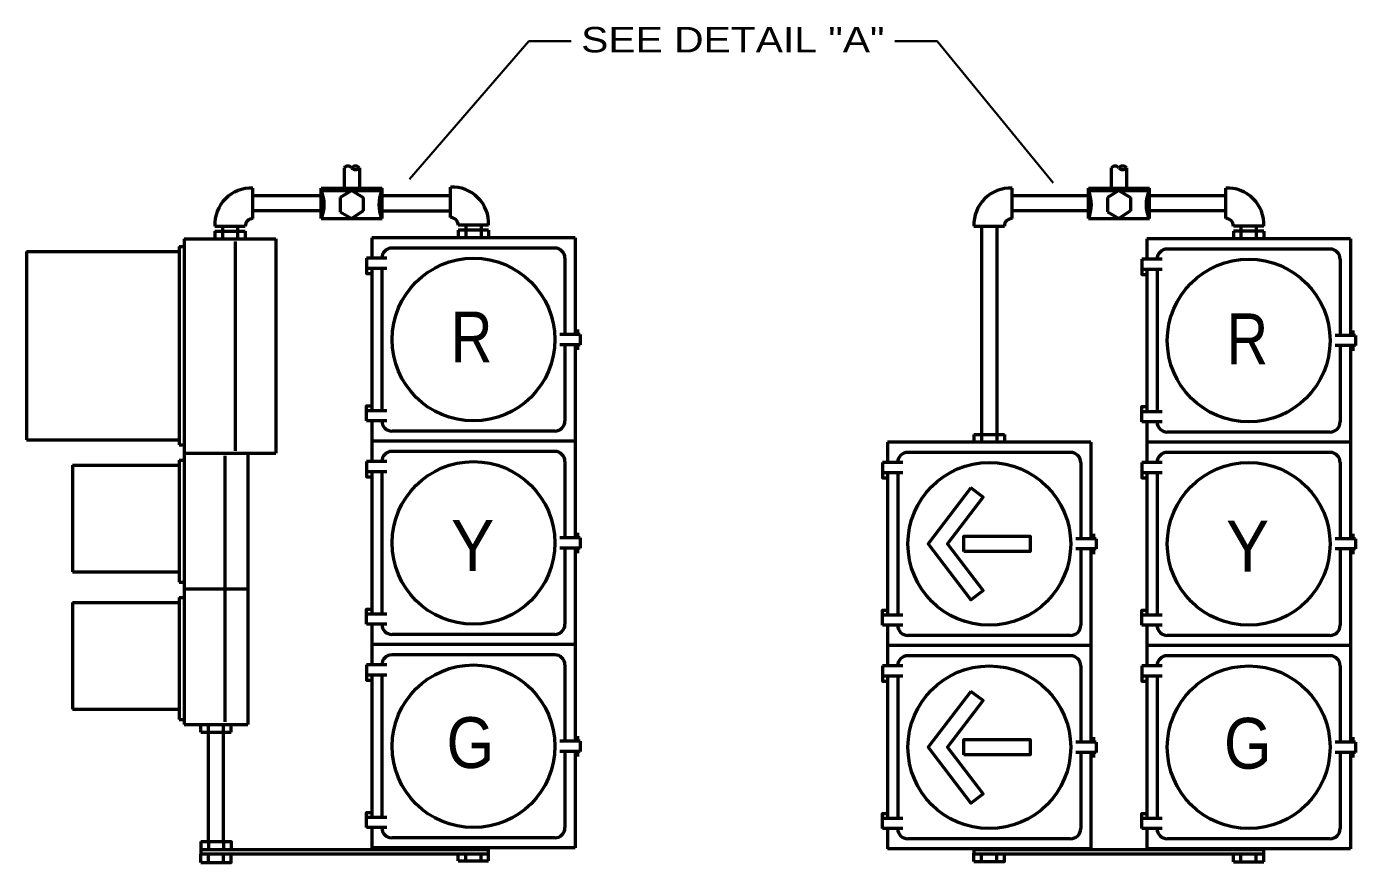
# Model space of a CAD drawing. Extents: x -382 to 473, y -132 to 412.
# Drawn here: x -262.8 to -106, y 137.8 to 236.4 of the extents above; entities that cross this region are included whole.
import ezdxf
from ezdxf.enums import TextEntityAlignment as Align

# ---------------------------------------------------------------- set-up
doc = ezdxf.new("R2010")
doc.units = 0
doc.header["$LTSCALE"] = 1.1
doc.layers.add('1', color=7, linetype='Continuous', lineweight=53)

msp = doc.modelspace()

# ---------------------------------------------------------------- linework, layer by layer
at = {"layer": '1', "lineweight": 35}
for p, q in [((-203.526, 234.737), (-217.631, 218.457)), ((-203.526, 234.737), (-198.535, 234.737)), ((-160.344, 234.737), (-155.353, 234.737)), ((-155.353, 234.737), (-141.683, 218.023))]:
    msp.add_line(p, q, dxfattribs=at)
at = {"layer": '1'}
for p, q in [((-225.335, 219.784), (-225.335, 217.384)), ((-223.535, 219.784), (-223.535, 217.384)), ((-134.828, 219.784), (-134.828, 217.384)), ((-133.028, 219.784), (-133.028, 217.384)), ((-236.09, 213.784), (-236.09, 217.384)), ((-236.09, 216.494), (-228.035, 216.494)), ((-228.035, 217.384), (-220.835, 217.384)), ((-228.035, 217.084), (-220.835, 217.084)), ((-224.435, 217.084), (-225.785, 216.274)), ((-224.435, 217.084), (-223.085, 216.274)), ((-220.835, 213.784), (-220.835, 217.384)), ((-220.835, 216.494), (-212.78, 216.494)), ((-212.78, 213.908), (-212.78, 217.508)), ((-146.528, 213.784), (-146.528, 217.384)), ((-137.528, 216.484), (-146.528, 216.484)), ((-137.528, 217.384), (-130.328, 217.384)), ((-137.528, 217.084), (-130.328, 217.084)), ((-133.928, 217.084), (-135.278, 216.274)), ((-133.928, 217.084), (-132.578, 216.274)), ((-130.328, 213.784), (-130.328, 217.384)), ((-121.328, 216.484), (-130.328, 216.484)), ((-121.328, 213.794), (-121.328, 217.394)), ((-225.785, 216.274), (-225.785, 214.594)), ((-223.085, 216.274), (-223.085, 214.714)), ((-135.278, 216.274), (-135.278, 214.594)), ((-132.578, 216.274), (-132.578, 214.714)), ((-228.035, 214.684), (-236.09, 214.684)), ((-228.035, 213.784), (-220.835, 213.784)), ((-225.785, 214.594), (-224.435, 213.784)), ((-223.085, 214.714), (-224.435, 213.784)), ((-220.835, 214.694), (-212.78, 214.694)), ((-137.528, 214.684), (-146.528, 214.684)), ((-137.528, 213.784), (-130.328, 213.784)), ((-135.278, 214.594), (-133.928, 213.784)), ((-132.578, 214.714), (-133.928, 213.784)), ((-121.328, 214.684), (-130.328, 214.684)), ((-240.59, 212.884), (-236.99, 212.884)), ((-240.59, 212.284), (-240.59, 211.384)), ((-240.59, 212.284), (-236.99, 212.284)), ((-239.69, 212.884), (-239.69, 211.384)), ((-237.89, 212.884), (-237.89, 211.384)), ((-236.99, 212.284), (-236.99, 211.384)), ((-208.28, 213.008), (-211.88, 213.008)), ((-211.88, 212.408), (-211.88, 211.508)), ((-208.28, 212.408), (-211.88, 212.408)), ((-210.98, 213.008), (-210.98, 211.508)), ((-209.18, 213.008), (-209.18, 211.508)), ((-208.28, 212.408), (-208.28, 211.508)), ((-151.028, 212.884), (-147.428, 212.884)), ((-150.128, 212.884), (-150.128, 187.394)), ((-148.328, 212.884), (-148.328, 187.394)), ((-116.828, 212.894), (-120.428, 212.894)), ((-120.428, 212.294), (-120.428, 211.394)), ((-116.828, 212.294), (-120.428, 212.294)), ((-119.528, 212.894), (-119.528, 211.394)), ((-117.728, 212.894), (-117.728, 211.394)), ((-116.828, 212.294), (-116.828, 211.394)), ((-244.79, 210.484), (-244.19, 210.484)), ((-244.79, 210.484), (-244.79, 187.084)), ((-244.19, 211.384), (-244.19, 154.084)), ((-244.19, 211.384), (-233.39, 211.384)), ((-238.19, 211.084), (-238.19, 186.388)), ((-233.39, 211.384), (-233.39, 186.088)), ((-198.08, 211.508), (-222.08, 211.508)), ((-222.08, 211.508), (-222.08, 209.108)), ((-200.48, 210.308), (-219.68, 210.308)), ((-198.08, 211.508), (-198.08, 200.108)), ((-106.628, 211.394), (-130.628, 211.394)), ((-130.628, 211.394), (-130.628, 208.994)), ((-109.028, 210.194), (-128.228, 210.194)), ((-106.628, 211.394), (-106.628, 199.994)), ((-262.79, 209.884), (-244.79, 209.884)), ((-262.79, 209.884), (-262.79, 187.684)), ((-220.28, 209.108), (-222.68, 209.108)), ((-199.28, 209.108), (-199.28, 200.108)), ((-128.828, 208.994), (-131.228, 208.994)), ((-107.828, 208.994), (-107.828, 199.994)), ((-220.28, 207.908), (-222.68, 207.908)), ((-222.08, 207.908), (-222.08, 191.108)), ((-220.88, 207.908), (-220.88, 191.108)), ((-128.828, 207.794), (-131.228, 207.794)), ((-130.628, 207.794), (-130.628, 190.994)), ((-129.428, 207.794), (-129.428, 190.994)), ((-197.78, 200.708), (-197.78, 200.108)), ((-197.48, 200.108), (-199.88, 200.108)), ((-197.48, 200.108), (-197.48, 198.908)), ((-106.028, 199.994), (-108.428, 199.994)), ((-106.328, 200.594), (-106.328, 199.994)), ((-106.028, 199.994), (-106.028, 198.794)), ((-197.48, 198.908), (-199.88, 198.908)), ((-199.28, 198.908), (-199.28, 189.908)), ((-198.08, 198.908), (-198.08, 187.508)), ((-197.78, 198.908), (-197.78, 198.308)), ((-106.028, 198.794), (-108.428, 198.794)), ((-107.828, 198.794), (-107.828, 189.794)), ((-106.628, 198.794), (-106.628, 187.394)), ((-106.328, 198.794), (-106.328, 198.194)), ((-220.28, 191.108), (-222.68, 191.108)), ((-220.28, 189.908), (-222.68, 189.908)), ((-222.08, 189.908), (-222.08, 187.508)), ((-128.828, 190.994), (-131.228, 190.994)), ((-128.828, 189.794), (-131.228, 189.794)), ((-130.628, 189.794), (-130.628, 187.394)), ((-200.48, 188.708), (-219.68, 188.708)), ((-151.028, 188.294), (-151.028, 187.394)), ((-151.028, 188.294), (-147.428, 188.294)), ((-147.428, 188.294), (-147.428, 187.394)), ((-109.028, 188.594), (-128.228, 188.594)), ((-262.79, 187.684), (-244.79, 187.684)), ((-244.79, 187.084), (-244.19, 187.084)), ((-198.08, 187.508), (-222.08, 187.508)), ((-222.08, 187.508), (-222.08, 185.108)), ((-198.08, 187.508), (-198.08, 176.108)), ((-137.228, 187.394), (-161.228, 187.394)), ((-161.228, 187.394), (-161.228, 184.994)), ((-137.228, 187.394), (-137.228, 175.994)), ((-106.628, 187.394), (-130.628, 187.394)), ((-130.628, 187.394), (-130.628, 184.994)), ((-106.628, 187.394), (-106.628, 175.994)), ((-244.79, 185.284), (-244.79, 170.884)), ((-244.79, 185.284), (-244.19, 185.284)), ((-244.19, 186.088), (-233.39, 186.088)), ((-239.39, 185.788), (-239.39, 154.384)), ((-236.69, 186.088), (-236.69, 154.084)), ((-220.28, 185.108), (-222.68, 185.108)), ((-200.48, 186.308), (-219.68, 186.308)), ((-199.28, 185.108), (-199.28, 176.108)), ((-159.428, 184.994), (-161.828, 184.994)), ((-139.628, 186.194), (-158.828, 186.194)), ((-138.428, 184.994), (-138.428, 175.994)), ((-128.828, 184.994), (-131.228, 184.994)), ((-109.028, 186.194), (-128.228, 186.194)), ((-107.828, 184.994), (-107.828, 175.994)), ((-257.39, 184.684), (-244.79, 184.684)), ((-257.39, 184.684), (-257.39, 172.084)), ((-220.28, 183.908), (-222.68, 183.908)), ((-222.08, 183.908), (-222.08, 167.108)), ((-220.88, 183.908), (-220.88, 167.108)), ((-159.428, 183.794), (-161.828, 183.794)), ((-161.228, 183.794), (-161.228, 166.994)), ((-160.028, 183.794), (-160.028, 166.994)), ((-128.828, 183.794), (-131.228, 183.794)), ((-130.628, 183.794), (-130.628, 166.994)), ((-129.428, 183.794), (-129.428, 166.994)), ((-197.48, 176.108), (-199.88, 176.108)), ((-197.78, 176.708), (-197.78, 176.108)), ((-197.48, 176.108), (-197.48, 174.908)), ((-136.628, 175.994), (-139.028, 175.994)), ((-136.928, 176.594), (-136.928, 175.994)), ((-136.628, 175.994), (-136.628, 174.794)), ((-106.028, 175.994), (-108.428, 175.994)), ((-106.328, 176.594), (-106.328, 175.994)), ((-106.028, 175.994), (-106.028, 174.794)), ((-197.48, 174.908), (-199.88, 174.908)), ((-199.28, 174.908), (-199.28, 165.908)), ((-198.08, 174.908), (-198.08, 163.508)), ((-197.78, 174.908), (-197.78, 174.308)), ((-136.628, 174.794), (-139.028, 174.794)), ((-138.428, 174.794), (-138.428, 165.794)), ((-137.228, 174.794), (-137.228, 163.394)), ((-136.928, 174.794), (-136.928, 174.194)), ((-106.028, 174.794), (-108.428, 174.794)), ((-107.828, 174.794), (-107.828, 165.794)), ((-106.628, 174.794), (-106.628, 163.394)), ((-106.328, 174.794), (-106.328, 174.194)), ((-257.39, 172.084), (-244.79, 172.084)), ((-244.79, 170.884), (-244.19, 170.884)), ((-244.19, 170.08), (-236.69, 170.08)), ((-257.39, 168.484), (-244.79, 168.484)), ((-257.39, 168.484), (-257.39, 155.884)), ((-244.79, 169.084), (-244.79, 154.684)), ((-244.79, 169.084), (-244.19, 169.084)), ((-220.28, 167.108), (-222.68, 167.108)), ((-159.428, 166.994), (-161.828, 166.994)), ((-128.828, 166.994), (-131.228, 166.994)), ((-220.28, 165.908), (-222.68, 165.908)), ((-222.08, 165.908), (-222.08, 163.508)), ((-200.48, 164.708), (-219.68, 164.708)), ((-159.428, 165.794), (-161.828, 165.794)), ((-161.228, 165.794), (-161.228, 163.394)), ((-128.828, 165.794), (-131.228, 165.794)), ((-130.628, 165.794), (-130.628, 163.394)), ((-198.08, 163.508), (-222.08, 163.508)), ((-222.08, 163.508), (-222.08, 161.108)), ((-198.08, 163.508), (-198.08, 152.108)), ((-137.228, 163.394), (-161.228, 163.394)), ((-161.228, 163.394), (-161.228, 160.994)), ((-139.628, 164.594), (-158.828, 164.594)), ((-137.228, 163.394), (-137.228, 151.994)), ((-106.628, 163.394), (-130.628, 163.394)), ((-130.628, 163.394), (-130.628, 160.994)), ((-109.028, 164.594), (-128.228, 164.594)), ((-106.628, 163.394), (-106.628, 151.994)), ((-200.48, 162.308), (-219.68, 162.308)), ((-139.628, 162.194), (-158.828, 162.194)), ((-109.028, 162.194), (-128.228, 162.194)), ((-220.28, 161.108), (-222.68, 161.108)), ((-220.28, 159.908), (-222.68, 159.908)), ((-222.08, 159.908), (-222.08, 143.108)), ((-220.88, 159.908), (-220.88, 143.108)), ((-199.28, 161.108), (-199.28, 152.108)), ((-159.428, 160.994), (-161.828, 160.994)), ((-138.428, 160.994), (-138.428, 151.994)), ((-128.828, 160.994), (-131.228, 160.994)), ((-107.828, 160.994), (-107.828, 151.994)), ((-159.428, 159.794), (-161.828, 159.794)), ((-161.228, 159.794), (-161.228, 142.994)), ((-160.028, 159.794), (-160.028, 142.994)), ((-128.828, 159.794), (-131.228, 159.794)), ((-130.628, 159.794), (-130.628, 142.994)), ((-129.428, 159.794), (-129.428, 142.994)), ((-257.39, 155.884), (-244.79, 155.884)), ((-244.79, 154.684), (-244.19, 154.684)), ((-244.19, 154.084), (-236.69, 154.084)), ((-242.24, 153.19), (-242.24, 154.09)), ((-238.64, 153.19), (-238.64, 154.09)), ((-242.24, 153.19), (-238.64, 153.19)), ((-197.48, 152.108), (-199.88, 152.108)), ((-197.78, 152.708), (-197.78, 152.108)), ((-197.48, 152.108), (-197.48, 150.908)), ((-136.928, 152.594), (-136.928, 151.994)), ((-106.328, 152.594), (-106.328, 151.994)), ((-197.48, 150.908), (-199.88, 150.908)), ((-199.28, 150.908), (-199.28, 141.908)), ((-198.08, 150.908), (-198.08, 139.508)), ((-197.78, 150.908), (-197.78, 150.308)), ((-136.628, 151.994), (-139.028, 151.994)), ((-136.628, 150.794), (-139.028, 150.794)), ((-138.428, 150.794), (-138.428, 141.794)), ((-137.228, 150.794), (-137.228, 139.394)), ((-136.928, 150.794), (-136.928, 150.194)), ((-136.628, 151.994), (-136.628, 150.794)), ((-106.028, 151.994), (-108.428, 151.994)), ((-106.028, 150.794), (-108.428, 150.794)), ((-107.828, 150.794), (-107.828, 141.794)), ((-106.628, 150.794), (-106.628, 139.394)), ((-106.328, 150.794), (-106.328, 150.194)), ((-106.028, 151.994), (-106.028, 150.794)), ((-220.28, 143.108), (-222.68, 143.108)), ((-159.428, 142.994), (-161.828, 142.994)), ((-128.828, 142.994), (-131.228, 142.994)), ((-220.28, 141.908), (-222.68, 141.908)), ((-222.08, 141.908), (-222.08, 139.508)), ((-159.428, 141.794), (-161.828, 141.794)), ((-161.228, 141.794), (-161.228, 139.394)), ((-128.828, 141.794), (-131.228, 141.794)), ((-130.628, 141.794), (-130.628, 139.394)), ((-241.34, 140.265), (-241.34, 139.274)), ((-239.54, 140.265), (-239.54, 139.274)), ((-200.48, 140.708), (-219.68, 140.708)), ((-139.628, 140.594), (-158.828, 140.594)), ((-109.028, 140.594), (-128.228, 140.594)), ((-208.28, 139.274), (-242.24, 139.274)), ((-242.24, 137.804), (-242.24, 138.795)), ((-208.28, 138.794), (-242.24, 138.794)), ((-241.34, 137.804), (-241.34, 138.795)), ((-239.54, 137.804), (-239.54, 138.795)), ((-198.08, 139.508), (-222.08, 139.508)), ((-211.88, 138.008), (-211.88, 138.908)), ((-211.88, 138.008), (-208.28, 138.008)), ((-210.98, 138.008), (-210.98, 138.908)), ((-209.18, 138.008), (-209.18, 138.908)), ((-208.28, 138.008), (-208.28, 139.508)), ((-137.228, 139.394), (-161.228, 139.394)), ((-151.028, 139.394), (-151.028, 138.914)), ((-116.828, 139.274), (-151.028, 139.274)), ((-151.028, 137.924), (-151.028, 138.915)), ((-116.828, 138.794), (-151.028, 138.794)), ((-150.128, 137.924), (-150.128, 138.794)), ((-148.328, 137.924), (-148.328, 138.794)), ((-106.628, 139.394), (-130.628, 139.394)), ((-120.428, 137.894), (-120.428, 138.794)), ((-119.528, 137.894), (-119.528, 138.794)), ((-117.728, 137.894), (-117.728, 138.794)), ((-116.828, 137.894), (-116.828, 139.394)), ((-120.428, 137.894), (-116.828, 137.894))]:
    msp.add_line(p, q, dxfattribs=at)
for points in [[(-228.035, 213.784), (-228.035, 217.084), (-228.035, 217.384)], [(-137.528, 213.784), (-137.528, 217.084), (-137.528, 217.384)], [(-222.68, 209.108), (-222.68, 207.308), (-222.08, 207.308)], [(-131.228, 208.994), (-131.228, 207.194), (-130.628, 207.194)], [(-222.68, 189.908), (-222.68, 191.708), (-222.08, 191.708)], [(-131.228, 189.794), (-131.228, 191.594), (-130.628, 191.594)], [(-222.68, 185.108), (-222.68, 183.308), (-222.08, 183.308)], [(-161.828, 184.994), (-161.828, 183.194), (-161.228, 183.194)], [(-131.228, 184.994), (-131.228, 183.194), (-130.628, 183.194)], [(-222.68, 165.908), (-222.68, 167.708), (-222.08, 167.708)], [(-161.828, 165.794), (-161.828, 167.594), (-161.228, 167.594)], [(-131.228, 165.794), (-131.228, 167.594), (-130.628, 167.594)], [(-222.68, 161.108), (-222.68, 159.308), (-222.08, 159.308)], [(-161.828, 160.994), (-161.828, 159.194), (-161.228, 159.194)], [(-131.228, 160.994), (-131.228, 159.194), (-130.628, 159.194)], [(-241.34, 140.265), (-241.34, 153.19), (-241.34, 154.09)], [(-239.54, 140.265), (-239.54, 153.19), (-239.54, 154.09)], [(-222.68, 141.908), (-222.68, 143.708), (-222.08, 143.708)], [(-161.828, 141.794), (-161.828, 143.594), (-161.228, 143.594)], [(-131.228, 141.794), (-131.228, 143.594), (-130.628, 143.594)], [(-242.24, 140.265), (-238.64, 140.265), (-238.64, 139.274)], [(-242.24, 140.265), (-242.24, 139.274), (-242.24, 138.794)], [(-242.24, 137.804), (-238.64, 137.804), (-238.64, 138.795)], [(-151.028, 137.924), (-147.428, 137.924), (-147.428, 138.794)]]:
    msp.add_lwpolyline(points, dxfattribs=at)
for points in [[(-151.391, 181.994), (-156.417, 175.394), (-151.387, 168.794), (-149.955, 169.885), (-154.155, 175.395), (-149.959, 180.904)], [(-152.217, 174.494), (-152.217, 176.294), (-144.417, 176.294), (-144.417, 174.494)], [(-151.391, 157.994), (-156.417, 151.394), (-151.387, 144.794), (-149.955, 145.885), (-154.155, 151.395), (-149.959, 156.904)], [(-152.217, 150.494), (-152.217, 152.294), (-144.417, 152.294), (-144.417, 150.494)]]:
    msp.add_lwpolyline(points, close=True, dxfattribs=at)
for centre in [(-210.069, 199.51), (-118.617, 199.396), (-210.069, 175.51), (-149.217, 175.396), (-118.617, 175.396), (-210.069, 151.51), (-149.217, 151.396), (-118.617, 151.396)]:
    msp.add_circle(centre, 9.6, dxfattribs=at)
for centre, radius, start, end in [((-224.885, 219.364), 0.616, 43.04811, 136.95189), ((-223.985, 219.364), 0.616, 43.04811, 136.95189), ((-223.985, 220.2), 0.616, 223.04811, 316.95189), ((-134.378, 219.364), 0.616, 43.04811, 136.95189), ((-133.478, 219.364), 0.616, 43.04811, 136.95189), ((-133.478, 220.2), 0.616, 223.04811, 316.95189), ((-236.28, 213.073), 4.315, 87.48391, 182.51609), ((-231.697, 215.434), 4.017, 335.74702, 24.25298), ((-217.209, 215.434), 4.017, 155.74702, 204.25298), ((-212.59, 213.197), 4.315, 357.48391, 92.51609), ((-146.718, 213.073), 4.315, 87.48391, 182.51609), ((-141.191, 215.434), 4.017, 335.74702, 24.25298), ((-126.703, 215.434), 4.017, 155.74702, 204.25298), ((-121.139, 213.083), 4.315, 357.48391, 92.51609), ((-236.134, 212.928), 0.857, 87.04875, 182.95125), ((-212.736, 213.052), 0.857, 357.04875, 92.95125), ((-146.572, 212.928), 0.857, 87.04875, 182.95125), ((-121.284, 212.938), 0.857, 357.04875, 92.95125), ((-219.68, 209.108), 1.2, 90, 180), ((-200.48, 209.108), 1.2, 0, 90), ((-128.228, 208.994), 1.2, 90, 180), ((-109.028, 208.994), 1.2, 0, 90), ((-219.68, 189.908), 1.2, 180, 270), ((-200.48, 189.908), 1.2, 270, 0), ((-128.228, 189.794), 1.2, 180, 270), ((-109.028, 189.794), 1.2, 270, 0), ((-219.68, 185.108), 1.2, 90, 180), ((-200.48, 185.108), 1.2, 0, 90), ((-158.828, 184.994), 1.2, 90, 180), ((-139.628, 184.994), 1.2, 0, 90), ((-128.228, 184.994), 1.2, 90, 180), ((-109.028, 184.994), 1.2, 0, 90), ((-219.68, 165.908), 1.2, 180, 270), ((-200.48, 165.908), 1.2, 270, 0), ((-158.828, 165.794), 1.2, 180, 270), ((-139.628, 165.794), 1.2, 270, 0), ((-128.228, 165.794), 1.2, 180, 270), ((-109.028, 165.794), 1.2, 270, 0), ((-219.68, 161.108), 1.2, 90, 180), ((-200.48, 161.108), 1.2, 0, 90), ((-158.828, 160.994), 1.2, 90, 180), ((-139.628, 160.994), 1.2, 0, 90), ((-128.228, 160.994), 1.2, 90, 180), ((-109.028, 160.994), 1.2, 0, 90), ((-219.68, 141.908), 1.2, 180, 270), ((-200.48, 141.908), 1.2, 270, 0), ((-158.828, 141.794), 1.2, 180, 270), ((-139.628, 141.794), 1.2, 270, 0), ((-128.228, 141.794), 1.2, 180, 270), ((-109.028, 141.794), 1.2, 270, 0)]:
    msp.add_arc(centre, radius, start, end, dxfattribs=at)

# ---------------------------------------------------------------- texts
at = {"layer": '1', "width": 1.2}
msp.add_text('SEE DETAIL "A"', height=3, dxfattribs=at).set_placement((-179.475, 233.404), align=Align.CENTER)
at = {"layer": '1'}
for s, width, p in [('R', 0.85, (-212.756, 196.814)), ('R', 0.85, (-121.245, 196.595)), ('Y', 0.95, (-212.706, 172.202)), ('Y', 0.95, (-121.289, 172.135)), ('G', 0.9, (-213.249, 148.947)), ('G', 0.9, (-121.534, 148.866))]:
    msp.add_text(s, height=6, dxfattribs=dict(at, width=width)).set_placement(p)

doc.saveas('drawing.dxf')
